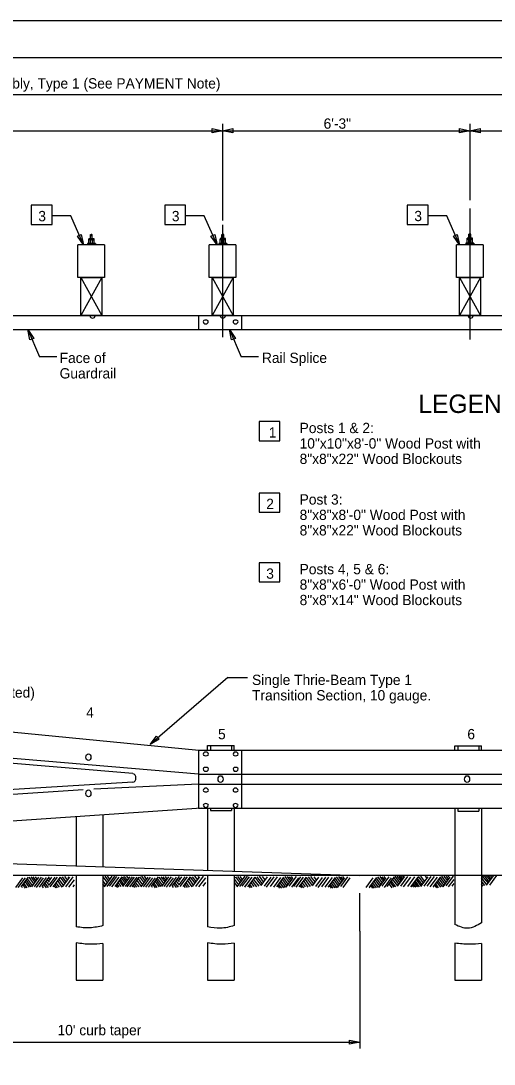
# Model space of a CAD drawing. Extents: x 0 to 34, y 0 to 22.
# Drawn here: x 12.13 to 18.56, y 7.81 to 22 of the extents above; entities that cross this region are included whole.
import ezdxf

# ---------------------------------------------------------------- set-up
doc = ezdxf.new("R2010")
doc.units = 0
for name, color, linetype in [('SH_Border', 7, 'Continuous'), ('SH_Cut_Line', 7, 'Continuous'), ('ST_Details', 7, 'Continuous'), ('ST_Text', 7, 'Continuous')]:
    doc.layers.add(name, color=color, linetype=linetype)

msp = doc.modelspace()

# ---------------------------------------------------------------- linework, layer by layer
at = {"layer": 'SH_Border'}
msp.add_lwpolyline([(2, 21.5), (33.5, 21.5), (33.5, 0.5), (2, 0.5)], close=True, dxfattribs=at)
at = {"layer": 'SH_Cut_Line'}
msp.add_lwpolyline([(0, 0), (34, 0), (34, 22), (0, 22)], close=True, dxfattribs=at)
at = {"layer": 'ST_Details'}
for p, q in [((18.23, 19.449), (18.23, 17.664)), ((14.87, 19.227), (14.87, 17.698)), ((13.124, 19.037), (13.053, 19.037)), ((13.053, 18.971), (13.053, 19.036)), ((13.073, 19.094), (13.081, 19.096)), ((13.073, 19.043), (13.073, 19.094)), ((13.099, 19.09), (13.073, 19.09)), ((13.099, 19.083), (13.073, 19.083)), ((13.099, 19.075), (13.073, 19.075)), ((13.073, 18.97), (13.073, 19.015)), ((13.092, 19.096), (13.084, 19.096)), ((13.099, 19.092), (13.092, 19.096)), ((13.099, 19.041), (13.099, 19.092)), ((13.1, 18.97), (13.1, 19.015)), ((13.124, 18.969), (13.124, 19.037)), ((14.91, 19.038), (14.839, 19.038)), ((14.839, 18.972), (14.839, 19.037)), ((14.859, 19.095), (14.867, 19.096)), ((14.859, 19.044), (14.859, 19.095)), ((14.885, 19.091), (14.859, 19.091)), ((14.885, 19.084), (14.859, 19.084)), ((14.885, 19.076), (14.859, 19.076)), ((14.859, 18.971), (14.859, 19.016)), ((14.878, 19.096), (14.87, 19.096)), ((14.885, 19.093), (14.878, 19.096)), ((14.885, 19.042), (14.885, 19.093)), ((14.885, 18.971), (14.885, 19.016)), ((14.91, 18.97), (14.91, 19.038)), ((18.268, 19.043), (18.196, 19.043)), ((18.196, 18.978), (18.196, 19.043)), ((18.217, 19.101), (18.225, 19.102)), ((18.217, 19.05), (18.217, 19.101)), ((18.242, 19.096), (18.217, 19.096)), ((18.242, 19.09), (18.217, 19.09)), ((18.242, 19.082), (18.217, 19.082)), ((18.217, 18.977), (18.217, 19.022)), ((18.236, 19.102), (18.227, 19.102)), ((18.242, 19.099), (18.236, 19.102)), ((18.242, 19.048), (18.242, 19.099)), ((18.243, 18.977), (18.243, 19.022)), ((18.268, 18.976), (18.268, 19.043)), ((12.904, 18.509), (12.904, 18.953)), ((13.266, 18.953), (12.904, 18.953)), ((13.142, 18.953), (13.031, 18.953)), ((13.142, 18.97), (13.033, 18.97)), ((13.033, 18.97), (13.033, 18.953)), ((13.142, 18.97), (13.142, 18.953)), ((13.266, 18.953), (13.266, 18.509)), ((14.689, 18.509), (14.689, 18.953)), ((15.051, 18.953), (14.689, 18.953)), ((14.928, 18.954), (14.817, 18.954)), ((14.927, 18.971), (14.819, 18.971)), ((14.819, 18.971), (14.819, 18.954)), ((14.927, 18.971), (14.927, 18.954)), ((15.051, 18.953), (15.051, 18.509)), ((18.051, 18.509), (18.051, 18.953)), ((18.413, 18.953), (18.051, 18.953)), ((18.285, 18.96), (18.175, 18.96)), ((18.285, 18.977), (18.177, 18.977)), ((18.177, 18.977), (18.177, 18.96)), ((18.285, 18.977), (18.285, 18.96)), ((18.413, 18.953), (18.413, 18.509)), ((13.266, 18.509), (12.904, 18.509)), ((12.942, 17.993), (12.942, 18.509)), ((12.942, 18.509), (13.227, 18.509)), ((12.942, 18.509), (13.227, 17.993)), ((13.227, 18.509), (12.942, 17.993)), ((13.227, 18.509), (13.227, 17.993)), ((15.051, 18.509), (14.689, 18.509)), ((14.727, 17.993), (14.727, 18.509)), ((14.727, 18.509), (15.013, 18.509)), ((14.727, 18.509), (15.013, 17.993)), ((15.013, 18.509), (14.727, 17.993)), ((15.013, 18.509), (15.013, 17.993)), ((18.413, 18.509), (18.051, 18.509)), ((18.089, 17.993), (18.089, 18.509)), ((18.089, 18.509), (18.375, 18.509)), ((18.089, 18.509), (18.375, 17.993)), ((18.375, 18.509), (18.089, 17.993)), ((18.375, 18.509), (18.375, 17.993)), ((4.502, 17.993), (21.269, 17.993)), ((13.227, 17.993), (12.942, 17.993)), ((14.546, 17.8), (14.546, 17.993)), ((15.013, 17.993), (14.727, 17.993)), ((15.028, 17.993), (14.742, 17.993)), ((15.131, 17.8), (15.131, 17.993)), ((18.375, 17.993), (18.089, 17.993)), ((5.407, 17.8), (21.269, 17.8)), ((11.535, 12.373), (14.546, 12.082)), ((14.546, 11.292), (14.546, 12.082)), ((14.546, 12.082), (21.854, 12.082)), ((14.667, 12.146), (15.029, 12.146)), ((14.667, 12.083), (14.667, 12.146)), ((14.705, 12.146), (14.705, 12.082)), ((14.99, 12.146), (14.99, 12.084)), ((15.029, 12.084), (15.029, 12.146)), ((15.131, 11.292), (15.131, 12.082)), ((18.028, 12.139), (18.391, 12.139)), ((18.028, 12.082), (18.028, 12.139)), ((18.066, 12.139), (18.066, 12.082)), ((18.352, 12.139), (18.352, 12.082)), ((18.391, 12.082), (18.391, 12.139)), ((13.651, 11.761), (11.53, 11.94)), ((14.544, 11.755), (11.533, 12.01)), ((13.046, 11.984), (13.046, 11.984)), ((13.651, 11.645), (11.531, 11.517)), ((14.544, 11.755), (15.199, 11.755)), ((14.842, 11.687), (14.842, 11.687)), ((15.199, 11.755), (21.269, 11.755)), ((18.194, 11.687), (18.194, 11.687)), ((12.975, 11.541), (11.533, 11.445)), ((14.544, 11.619), (13.118, 11.551)), ((14.544, 11.619), (15.199, 11.619)), ((15.199, 11.619), (21.269, 11.619)), ((14.582, 11.292), (11.535, 11.084)), ((14.544, 11.292), (15.199, 11.292)), ((14.667, 11.293), (14.667, 10.445)), ((14.705, 11.292), (14.705, 11.258)), ((14.705, 11.258), (14.99, 11.258)), ((14.99, 11.292), (14.99, 11.258)), ((15.029, 11.292), (15.029, 10.433)), ((15.199, 11.292), (21.854, 11.292)), ((18.028, 11.292), (18.028, 10.375)), ((18.066, 11.292), (18.066, 11.251)), ((18.066, 11.251), (18.352, 11.251)), ((18.352, 11.293), (18.352, 11.251)), ((18.391, 11.293), (18.391, 10.375)), ((12.881, 11.177), (12.881, 10.505)), ((13.244, 11.202), (13.244, 10.493)), ((11.028, 10.568), (16.736, 10.375)), ((13.244, 10.375), (11.674, 10.375)), ((12.35, 10.324), (12.325, 10.359)), ((12.418, 10.227), (12.515, 10.359)), ((12.765, 10.311), (12.726, 10.364)), ((12.738, 10.222), (12.84, 10.359)), ((12.783, 10.341), (12.769, 10.36)), ((12.881, 10.375), (12.881, 9.677)), ((13.244, 10.375), (13.244, 9.694)), ((15.029, 10.375), (13.244, 10.375)), ((13.301, 10.285), (13.245, 10.36)), ((13.265, 10.223), (13.371, 10.367)), ((13.322, 10.3), (13.273, 10.365)), ((13.3, 10.228), (13.403, 10.367)), ((13.338, 10.324), (13.307, 10.365)), ((13.334, 10.231), (13.431, 10.362)), ((14.61, 10.375), (13.478, 10.375)), ((13.564, 10.292), (13.514, 10.36)), ((13.576, 10.31), (13.537, 10.363)), ((13.591, 10.334), (13.567, 10.365)), ((13.801, 10.285), (13.745, 10.36)), ((13.821, 10.3), (13.773, 10.365)), ((13.837, 10.324), (13.807, 10.365)), ((14.092, 10.284), (14.036, 10.36)), ((14.103, 10.308), (14.064, 10.36)), ((14.118, 10.328), (14.092, 10.363)), ((14.185, 10.231), (14.282, 10.362)), ((14.511, 10.293), (14.461, 10.36)), ((14.532, 10.315), (14.494, 10.368)), ((14.505, 10.226), (14.609, 10.367)), ((14.55, 10.345), (14.536, 10.364)), ((14.667, 10.375), (14.667, 9.677)), ((15.029, 10.375), (15.029, 9.694)), ((16.247, 10.375), (15.029, 10.375)), ((15.069, 10.221), (15.175, 10.365)), ((15.126, 10.298), (15.077, 10.364)), ((15.104, 10.226), (15.207, 10.365)), ((15.142, 10.322), (15.111, 10.364)), ((15.138, 10.229), (15.235, 10.36)), ((15.16, 10.359), (15.161, 10.36)), ((15.428, 10.29), (15.372, 10.366)), ((15.447, 10.317), (15.414, 10.362)), ((15.779, 10.282), (15.719, 10.362)), ((15.798, 10.3), (15.75, 10.364)), ((15.777, 10.231), (15.874, 10.362)), ((15.81, 10.32), (15.78, 10.36)), ((15.825, 10.337), (15.805, 10.364)), ((16.127, 10.288), (16.071, 10.363)), ((16.146, 10.315), (16.113, 10.359)), ((18.391, 10.375), (16.247, 10.375)), ((16.478, 10.279), (16.418, 10.359)), ((16.497, 10.297), (16.449, 10.361)), ((16.476, 10.228), (16.573, 10.36)), ((16.524, 10.335), (16.505, 10.361)), ((17.04, 10.28), (16.981, 10.36)), ((17.059, 10.298), (17.011, 10.362)), ((17.038, 10.229), (17.136, 10.36)), ((17.086, 10.335), (17.066, 10.362)), ((17.281, 10.279), (17.216, 10.366)), ((17.295, 10.298), (17.242, 10.369)), ((17.248, 10.231), (17.345, 10.363)), ((17.309, 10.312), (17.27, 10.366)), ((17.292, 10.231), (17.389, 10.363)), ((17.321, 10.332), (17.293, 10.371)), ((17.337, 10.35), (17.321, 10.371)), ((17.602, 10.274), (17.535, 10.364)), ((17.614, 10.299), (17.564, 10.368)), ((17.609, 10.231), (17.706, 10.363)), ((17.648, 10.343), (17.628, 10.369)), ((17.652, 10.231), (17.749, 10.363)), ((17.911, 10.287), (17.852, 10.368)), ((17.93, 10.305), (17.883, 10.369)), ((17.909, 10.237), (18.007, 10.368)), ((17.942, 10.325), (17.912, 10.366)), ((17.957, 10.343), (17.938, 10.369)), ((18.028, 10.375), (18.028, 9.708)), ((18.39, 10.335), (18.417, 10.372)), ((18.391, 10.375), (18.391, 9.733)), ((21.752, 10.375), (18.391, 10.375)), ((18.478, 10.274), (18.414, 10.36)), ((18.491, 10.294), (18.43, 10.377)), ((18.505, 10.313), (18.458, 10.377)), ((18.459, 10.246), (18.555, 10.377)), ((18.52, 10.327), (18.483, 10.377)), ((18.502, 10.246), (18.599, 10.378)), ((18.532, 10.347), (18.51, 10.377)), ((18.548, 10.365), (18.538, 10.377)), ((12.058, 10.211), (12.155, 10.342)), ((12.093, 10.211), (12.191, 10.342)), ((12.133, 10.222), (12.23, 10.353)), ((12.152, 10.21), (12.139, 10.227)), ((12.191, 10.204), (12.158, 10.249)), ((12.215, 10.21), (12.172, 10.268)), ((12.244, 10.216), (12.186, 10.295)), ((12.27, 10.221), (12.2, 10.316)), ((12.285, 10.24), (12.22, 10.329)), ((12.308, 10.258), (12.239, 10.351)), ((12.325, 10.281), (12.269, 10.356)), ((12.276, 10.222), (12.373, 10.353)), ((12.335, 10.304), (12.297, 10.356)), ((12.311, 10.222), (12.408, 10.353)), ((12.339, 10.211), (12.436, 10.342)), ((12.379, 10.216), (12.476, 10.348)), ((12.437, 10.207), (12.42, 10.23)), ((12.477, 10.209), (12.441, 10.257)), ((12.504, 10.212), (12.455, 10.278)), ((12.516, 10.242), (12.477, 10.295)), ((12.516, 10.287), (12.493, 10.319)), ((12.516, 10.33), (12.509, 10.34)), ((12.516, 10.307), (12.55, 10.353)), ((12.516, 10.248), (12.594, 10.353)), ((12.528, 10.222), (12.625, 10.353)), ((12.568, 10.222), (12.665, 10.353)), ((12.601, 10.207), (12.578, 10.237)), ((12.628, 10.21), (12.595, 10.254)), ((12.653, 10.216), (12.609, 10.276)), ((12.69, 10.219), (12.633, 10.297)), ((12.709, 10.243), (12.65, 10.321)), ((12.728, 10.268), (12.666, 10.351)), ((12.743, 10.289), (12.694, 10.356)), ((12.695, 10.222), (12.792, 10.353)), ((12.782, 10.216), (12.855, 10.316)), ((12.837, 10.224), (12.855, 10.248)), ((13.284, 10.251), (13.242, 10.308)), ((13.268, 10.227), (13.242, 10.263)), ((13.304, 10.28), (13.303, 10.282)), ((13.366, 10.22), (13.463, 10.352)), ((13.409, 10.226), (13.506, 10.357)), ((13.445, 10.211), (13.421, 10.245)), ((13.465, 10.22), (13.434, 10.261)), ((13.493, 10.228), (13.452, 10.282)), ((13.518, 10.236), (13.468, 10.304)), ((13.531, 10.251), (13.48, 10.32)), ((13.548, 10.273), (13.496, 10.344)), ((13.516, 10.226), (13.613, 10.357)), ((13.548, 10.226), (13.645, 10.357)), ((13.575, 10.22), (13.673, 10.352)), ((13.611, 10.22), (13.708, 10.352)), ((13.639, 10.22), (13.736, 10.352)), ((13.679, 10.213), (13.655, 10.246)), ((13.706, 10.215), (13.674, 10.258)), ((13.734, 10.22), (13.688, 10.282)), ((13.768, 10.227), (13.708, 10.309)), ((13.784, 10.251), (13.725, 10.331)), ((13.762, 10.22), (13.859, 10.352)), ((13.793, 10.22), (13.89, 10.352)), ((13.804, 10.28), (13.803, 10.282)), ((13.825, 10.215), (13.922, 10.346)), ((13.861, 10.215), (13.958, 10.346)), ((13.9, 10.226), (13.997, 10.357)), ((13.919, 10.213), (13.906, 10.231)), ((13.958, 10.208), (13.925, 10.253)), ((13.982, 10.214), (13.939, 10.272)), ((14.011, 10.22), (13.953, 10.298)), ((14.037, 10.225), (13.967, 10.32)), ((14.053, 10.244), (13.987, 10.333)), ((14.075, 10.262), (14.007, 10.355)), ((14.043, 10.226), (14.14, 10.357)), ((14.078, 10.226), (14.175, 10.357)), ((14.106, 10.215), (14.203, 10.346)), ((14.146, 10.22), (14.243, 10.352)), ((14.204, 10.211), (14.187, 10.234)), ((14.244, 10.213), (14.208, 10.261)), ((14.272, 10.216), (14.222, 10.282)), ((14.283, 10.246), (14.244, 10.298)), ((14.283, 10.291), (14.26, 10.323)), ((14.283, 10.334), (14.276, 10.344)), ((14.283, 10.311), (14.317, 10.357)), ((14.283, 10.252), (14.361, 10.357)), ((14.295, 10.226), (14.393, 10.357)), ((14.335, 10.226), (14.432, 10.357)), ((14.368, 10.211), (14.345, 10.241)), ((14.395, 10.214), (14.362, 10.258)), ((14.421, 10.219), (14.376, 10.28)), ((14.457, 10.223), (14.4, 10.301)), ((14.476, 10.246), (14.418, 10.325)), ((14.495, 10.272), (14.433, 10.355)), ((14.462, 10.226), (14.559, 10.357)), ((14.549, 10.22), (14.64, 10.344)), ((14.605, 10.232), (14.64, 10.28)), ((15.035, 10.343), (15.04, 10.35)), ((15.089, 10.249), (15.035, 10.321)), ((15.072, 10.226), (15.035, 10.276)), ((15.038, 10.218), (15.035, 10.222)), ((15.105, 10.283), (15.05, 10.358)), ((15.108, 10.279), (15.108, 10.28)), ((15.17, 10.218), (15.267, 10.35)), ((15.174, 10.224), (15.271, 10.355)), ((15.213, 10.224), (15.311, 10.355)), ((15.249, 10.21), (15.225, 10.243)), ((15.274, 10.212), (15.241, 10.256)), ((15.297, 10.226), (15.257, 10.28)), ((15.336, 10.221), (15.278, 10.299)), ((15.366, 10.229), (15.296, 10.323)), ((15.393, 10.244), (15.312, 10.353)), ((15.409, 10.265), (15.34, 10.358)), ((15.394, 10.239), (15.481, 10.357)), ((15.439, 10.229), (15.53, 10.352)), ((15.469, 10.215), (15.573, 10.357)), ((15.52, 10.226), (15.617, 10.357)), ((15.566, 10.218), (15.663, 10.35)), ((15.607, 10.22), (15.704, 10.352)), ((15.608, 10.279), (15.607, 10.28)), ((15.649, 10.204), (15.622, 10.242)), ((15.673, 10.204), (15.636, 10.255)), ((15.703, 10.21), (15.653, 10.278)), ((15.73, 10.216), (15.668, 10.299)), ((15.745, 10.239), (15.687, 10.318)), ((15.762, 10.259), (15.701, 10.341)), ((15.723, 10.211), (15.71, 10.229)), ((15.734, 10.215), (15.831, 10.346)), ((15.809, 10.215), (15.906, 10.346)), ((15.837, 10.226), (15.934, 10.358)), ((15.859, 10.357), (15.86, 10.358)), ((15.869, 10.216), (15.966, 10.347)), ((15.873, 10.221), (15.97, 10.353)), ((15.912, 10.221), (16.01, 10.353)), ((15.948, 10.207), (15.924, 10.24)), ((15.973, 10.209), (15.94, 10.254)), ((15.996, 10.223), (15.956, 10.278)), ((16.035, 10.219), (15.977, 10.297)), ((16.065, 10.227), (15.995, 10.321)), ((16.092, 10.241), (16.011, 10.35)), ((16.108, 10.262), (16.039, 10.356)), ((16.093, 10.237), (16.18, 10.354)), ((16.138, 10.227), (16.229, 10.349)), ((16.168, 10.213), (16.272, 10.354)), ((16.219, 10.223), (16.316, 10.354)), ((16.265, 10.216), (16.362, 10.347)), ((16.306, 10.218), (16.403, 10.349)), ((16.307, 10.276), (16.306, 10.277)), ((16.349, 10.202), (16.321, 10.239)), ((16.372, 10.202), (16.335, 10.252)), ((16.402, 10.207), (16.352, 10.275)), ((16.429, 10.213), (16.368, 10.296)), ((16.445, 10.236), (16.386, 10.316)), ((16.461, 10.256), (16.4, 10.338)), ((16.422, 10.209), (16.409, 10.226)), ((16.433, 10.212), (16.53, 10.344)), ((16.509, 10.317), (16.479, 10.357)), ((16.508, 10.212), (16.605, 10.344)), ((16.821, 10.213), (16.918, 10.344)), ((16.87, 10.21), (16.863, 10.219)), ((16.868, 10.218), (16.965, 10.35)), ((16.911, 10.202), (16.883, 10.24)), ((16.935, 10.202), (16.897, 10.253)), ((16.964, 10.208), (16.914, 10.276)), ((16.991, 10.214), (16.93, 10.297)), ((17.006, 10.237), (16.948, 10.316)), ((17.023, 10.257), (16.962, 10.339)), ((16.995, 10.213), (17.092, 10.344)), ((17.071, 10.318), (17.041, 10.358)), ((17.07, 10.213), (17.167, 10.344)), ((17.109, 10.226), (17.207, 10.357)), ((17.175, 10.208), (17.139, 10.256)), ((17.201, 10.215), (17.155, 10.277)), ((17.226, 10.223), (17.168, 10.301)), ((17.25, 10.234), (17.185, 10.322)), ((17.267, 10.259), (17.203, 10.345)), ((17.331, 10.22), (17.429, 10.352)), ((17.387, 10.226), (17.484, 10.357)), ((17.43, 10.22), (17.527, 10.352)), ((17.453, 10.221), (17.442, 10.236)), ((17.478, 10.219), (17.455, 10.249)), ((17.502, 10.219), (17.466, 10.268)), ((17.522, 10.223), (17.478, 10.284)), ((17.547, 10.224), (17.49, 10.301)), ((17.568, 10.236), (17.506, 10.32)), ((17.584, 10.252), (17.521, 10.337)), ((17.565, 10.226), (17.662, 10.357)), ((17.692, 10.22), (17.789, 10.352)), ((17.741, 10.217), (17.734, 10.226)), ((17.739, 10.226), (17.836, 10.357)), ((17.782, 10.21), (17.754, 10.247)), ((17.806, 10.21), (17.768, 10.261)), ((17.835, 10.216), (17.785, 10.284)), ((17.862, 10.221), (17.801, 10.304)), ((17.878, 10.244), (17.819, 10.324)), ((17.894, 10.264), (17.833, 10.347)), ((17.866, 10.22), (17.963, 10.352)), ((17.941, 10.22), (18.016, 10.322)), ((17.989, 10.231), (18.016, 10.269)), ((18.436, 10.238), (18.39, 10.301)), ((18.411, 10.23), (18.39, 10.259)), ((18.461, 10.249), (18.396, 10.337)), ((12.881, 9.46), (12.881, 9.454)), ((12.881, 9.454), (12.881, 8.951)), ((13.244, 9.451), (13.244, 8.951)), ((14.666, 9.46), (14.666, 9.454)), ((14.666, 9.454), (14.666, 8.951)), ((15.029, 9.454), (15.029, 8.951)), ((18.028, 9.454), (18.028, 8.951)), ((18.391, 9.451), (18.391, 8.951)), ((12.881, 8.951), (13.244, 8.951)), ((14.666, 8.951), (15.029, 8.951)), ((18.028, 8.951), (18.391, 8.951))]:
    msp.add_line(p, q, dxfattribs=at)
for centre, major_axis, ratio, start_param, end_param in [((13.063, 19.019), (0, -0.0142), 0.738563, 1.441228, 4.934001), ((13.087, 19.018), (0, -0.0169), 0.738563, 1.385306, 4.820506), ((13.112, 19.017), (0, -0.0162), 0.738563, 1.407193, 4.875853), ((14.849, 19.02), (0, -0.0142), 0.738563, 1.441228, 4.934001), ((14.873, 19.019), (0, -0.0169), 0.738563, 1.385306, 4.820506), ((14.897, 19.018), (0, -0.0162), 0.738563, 1.407193, 4.875853), ((18.207, 19.026), (0, -0.0142), 0.738563, 1.441228, 4.934001), ((18.231, 19.025), (0, -0.0169), 0.738563, 1.385306, 4.820506), ((18.255, 19.023), (0, -0.0162), 0.738563, 1.407193, 4.875853), ((13.103, 17.989), (0.0342, 0), 0.943283, 3.141593, 6.283185), ((14.641, 17.91), (-0.0342, 0), 0.599655, 3.141593, 6.283185), ((14.641, 17.91), (0.0342, 0), 0.943283, 3.141593, 6.283185), ((14.873, 17.989), (0.0342, 0), 0.943283, 3.141593, 6.283185), ((15.046, 17.91), (-0.0342, 0), 0.599655, 3.141593, 6.283185), ((15.046, 17.91), (0.0342, 0), 0.943283, 3.141593, 6.283185), ((18.242, 17.989), (0.0342, 0), 0.943283, 3.141593, 6.283185), ((14.642, 12.024), (0.0342, 0), 0.920676, 0, 3.141593), ((14.642, 12.024), (-0.0342, 0), 0.587975, 0, 3.141593), ((15.046, 12.024), (0.0342, 0), 0.920676, 0, 3.141593), ((15.046, 12.024), (-0.0342, 0), 0.587975, 0, 3.141593), ((14.642, 11.825), (0.0342, 0), 0.599655, 0, 3.141593), ((14.642, 11.825), (-0.0342, 0), 0.943283, 0, 3.141593), ((15.046, 11.825), (0.0342, 0), 0.599655, 0, 3.141593), ((15.046, 11.825), (-0.0342, 0), 0.943283, 0, 3.141593), ((13.649, 11.703), (0, -0.058), 0.738563, 0.049283, 3.084561), ((14.642, 11.533), (-0.0342, 0), 0.943283, 3.141593, 6.283185), ((14.642, 11.533), (0.0342, 0), 0.599655, 3.141593, 6.283185), ((15.046, 11.533), (-0.0342, 0), 0.943283, 3.141593, 6.283185), ((15.046, 11.533), (0.0342, 0), 0.599655, 3.141593, 6.283185), ((14.642, 11.334), (-0.0342, 0), 0.587975, 3.141593, 6.283185), ((15.046, 11.334), (-0.0342, 0), 0.587975, 3.141593, 6.283185), ((14.642, 11.334), (0.0342, 0), 0.920676, 3.141593, 6.283185), ((15.046, 11.334), (0.0342, 0), 0.920676, 3.141593, 6.283185)]:
    msp.add_ellipse(centre, major_axis=major_axis, ratio=ratio, start_param=start_param, end_param=end_param, dxfattribs=at)
for centre in [(13.046, 11.985), (14.842, 11.687), (18.194, 11.687), (13.046, 11.493)]:
    msp.add_ellipse(centre, major_axis=(0, 0.0463), ratio=0.738563, dxfattribs=at)
for points in [[(13.244, 9.694), (13.067, 9.664), (12.881, 9.677)], [(15.029, 9.694), (14.841, 9.658), (14.667, 9.677)], [(18.391, 9.733), (18.203, 9.658), (18.028, 9.708)], [(13.244, 9.451), (13.078, 9.44), (12.881, 9.46)], [(15.029, 9.454), (14.864, 9.44), (14.666, 9.46)], [(18.391, 9.451), (18.225, 9.44), (18.028, 9.454)]]:
    msp.add_spline(points, degree=3, dxfattribs=at)
at = {"layer": 'ST_Text'}
for p, q in [((4.161, 20.997), (21.594, 20.997)), ((14.87, 20.598), (14.87, 19.285)), ((18.232, 20.598), (18.232, 19.563)), ((7.728, 20.506), (14.87, 20.506)), ((14.87, 20.506), (18.232, 20.506)), ((18.232, 20.506), (23.387, 20.506)), ((12.268, 19.494), (12.268, 19.232)), ((12.552, 19.494), (12.268, 19.494)), ((12.552, 19.232), (12.552, 19.494)), ((14.083, 19.494), (14.083, 19.232)), ((14.367, 19.494), (14.083, 19.494)), ((14.367, 19.232), (14.367, 19.494)), ((17.379, 19.494), (17.379, 19.232)), ((17.663, 19.494), (17.379, 19.494)), ((17.663, 19.232), (17.663, 19.494)), ((12.268, 19.232), (12.552, 19.232)), ((14.083, 19.232), (14.367, 19.232)), ((17.379, 19.232), (17.663, 19.232)), ((12.223, 17.8), (12.382, 17.429)), ((14.963, 17.8), (15.123, 17.429)), ((12.615, 17.429), (12.382, 17.429)), ((15.356, 17.429), (15.123, 17.429)), ((15.366, 16.551), (15.366, 16.289)), ((15.65, 16.551), (15.366, 16.551)), ((15.65, 16.289), (15.65, 16.551)), ((15.366, 16.289), (15.65, 16.289)), ((15.366, 15.578), (15.366, 15.316)), ((15.65, 15.578), (15.366, 15.578)), ((15.65, 15.316), (15.65, 15.578)), ((15.366, 15.316), (15.65, 15.316)), ((15.366, 14.63), (15.366, 14.369)), ((15.65, 14.63), (15.366, 14.63)), ((15.65, 14.369), (15.65, 14.63)), ((15.366, 14.369), (15.65, 14.369)), ((14.942, 13.07), (13.884, 12.158)), ((14.942, 13.07), (15.21, 13.07)), ((16.736, 9.62), (16.736, 10.135)), ((16.736, 9.62), (16.736, 8.023)), ((5.304, 8.109), (16.736, 8.109))]:
    msp.add_line(p, q, dxfattribs=at)
for points in [[(14.73, 20.478), (14.73, 20.534), (14.87, 20.506)], [(15.01, 20.534), (15.01, 20.478), (14.87, 20.506)], [(18.092, 20.478), (18.092, 20.534), (18.232, 20.506)], [(18.372, 20.534), (18.372, 20.478), (18.232, 20.506)], [(12.897, 19.071), (12.948, 19.094), (12.979, 18.955)], [(14.712, 19.071), (14.763, 19.094), (14.794, 18.955)], [(18.008, 19.072), (18.059, 19.095), (18.09, 18.955)], [(12.304, 17.682), (12.252, 17.66), (12.223, 17.8)], [(15.044, 17.682), (14.993, 17.66), (14.963, 17.8)], [(13.972, 12.271), (14.009, 12.228), (13.884, 12.158)], [(16.596, 8.081), (16.596, 8.137), (16.736, 8.109)]]:
    msp.add_lwpolyline(points, close=True, dxfattribs=at)
for points in [[(12.979, 18.955), (12.805, 19.348), (12.552, 19.348)], [(14.794, 18.955), (14.619, 19.348), (14.367, 19.348)], [(18.09, 18.955), (17.916, 19.348), (17.663, 19.348)]]:
    msp.add_lwpolyline(points, dxfattribs=at)

# ---------------------------------------------------------------- texts
for s, height, p in [('Item 606 Guardrail Type 5 and Item 606 Bridge Terminal Assembly, Type 1 (See PAYMENT Note)', 0.14, (6.694, 21.08)), ('6\'-3"', 0.14, (16.243, 20.533)), ('3', 0.14, (12.365, 19.275)), ('3', 0.14, (14.18, 19.275)), ('3', 0.14, (17.476, 19.276)), ('Face of', 0.14, (12.655, 17.346)), ('Rail Splice', 0.14, (15.405, 17.347)), ('Guardrail', 0.14, (12.655, 17.136)), ('LEGEND', 0.25, (17.531, 16.667)), ('1', 0.14, (15.498, 16.332)), ('Posts 1 & 2:', 0.14, (15.917, 16.393)), ('10"x10"x8\'-0" Wood Post with', 0.14, (15.917, 16.183)), ('8"x8"x22" Wood Blockouts', 0.14, (15.917, 15.973)), ('2', 0.14, (15.463, 15.36)), ('Post 3:', 0.14, (15.917, 15.421)), ('8"x8"x8\'-0" Wood Post with', 0.14, (15.917, 15.211)), ('8"x8"x22" Wood Blockouts', 0.14, (15.917, 15.001)), ('3', 0.14, (15.463, 14.412)), ('Posts 4, 5 & 6:', 0.14, (15.917, 14.473)), ('8"x8"x6\'-0" Wood Post with', 0.14, (15.917, 14.263)), ('8"x8"x14" Wood Blockouts', 0.14, (15.917, 14.053)), ('Single Thrie-Beam Type 1', 0.14, (15.27, 12.967)), ('Two Thrie-Beam Rail Sections (nested)', 0.14, (9.051, 12.795)), ('Transition Section, 10 gauge.', 0.14, (15.27, 12.757)), ('4', 0.14, (13.016, 12.523)), ('5', 0.14, (14.808, 12.229)), ('6', 0.14, (18.197, 12.229)), ("10' curb taper", 0.14, (12.626, 8.203))]:
    msp.add_text(s, height=height, dxfattribs=at).set_placement(p)

doc.saveas('drawing.dxf')
